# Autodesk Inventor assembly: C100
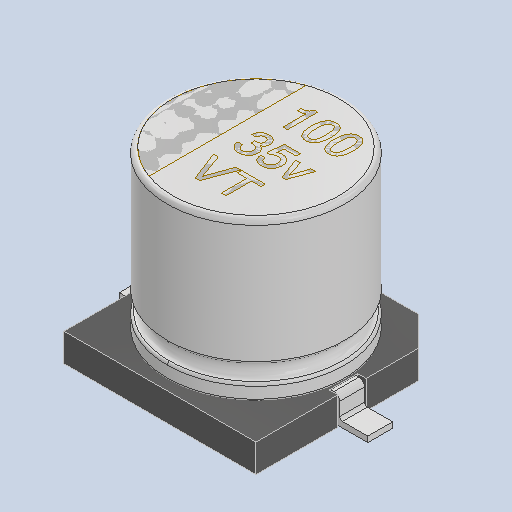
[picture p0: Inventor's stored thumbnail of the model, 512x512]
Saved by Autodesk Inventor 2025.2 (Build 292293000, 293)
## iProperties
Created: 2025-04
Part Number: C100
Description: PART--DESC
Document SubType Name: Assembly
Designer: BennF
Author: BennF
Revision Number: NONE
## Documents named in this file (4)
- C:\Users\BennF\Nextcloud\Benutzer\CNC JarBeRi\existing parts\Electronics\RepRap A4988 Shied (USE WITHOUT ARDUINO)\reprap-a4988-1.snapshot.1\RepRap\RepRap\C100_2.iam
- C:\Users\BennF\Nextcloud\Benutzer\CNC JarBeRi\existing parts\Electronics\RepRap A4988 Shied (USE WITHOUT ARDUINO)\reprap-a4988-1.snapshot.1\RepRap\RepRap\C100 Geometry.ipt
- C:\Users\BennF\Nextcloud\Benutzer\CNC JarBeRi\existing parts\Electronics\RepRap A4988 Shied (USE WITHOUT ARDUINO)\reprap-a4988-1.snapshot.1\RepRap\RepRap\name3.ipt
- C:\Users\BennF\Nextcloud\Benutzer\CNC JarBeRi\existing parts\Electronics\RepRap A4988 Shied (USE WITHOUT ARDUINO)\reprap-a4988-1.snapshot.1\RepRap\RepRap\bay_2.iam
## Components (3 placed, 3 different names)
1. C100 Geometry
2. name3
3. bay [sub-assembly]
